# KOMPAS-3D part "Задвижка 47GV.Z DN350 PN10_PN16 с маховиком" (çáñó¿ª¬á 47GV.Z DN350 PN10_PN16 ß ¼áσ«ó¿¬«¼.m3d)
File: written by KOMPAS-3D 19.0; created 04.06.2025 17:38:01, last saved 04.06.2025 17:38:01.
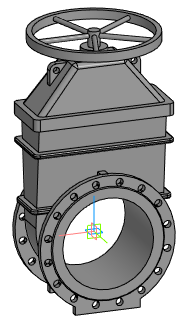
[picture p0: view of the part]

Document properties: Автор: Евгений; Полное имя файла: E:\Dendor Работа Сачек\3D для проекитирвщиков\2.1 Тип 47GV, 47GV.Z Задвижка клиновая фланцевая с обрезиненным клином\stp_Тип 47GV.Z. Задвижка DN40-DN350 с маховиком\Задвижка 47GV.Z DN350 PN10_PN16 с маховиком.m3d

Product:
- Part/product: Задвижка 47GV.Z DN350 PN10_PN16 с маховиком

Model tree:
1. Операция без истории:1  (labels: Задвижка 47GV.Z DN350 PN10_PN16 с маховиком)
